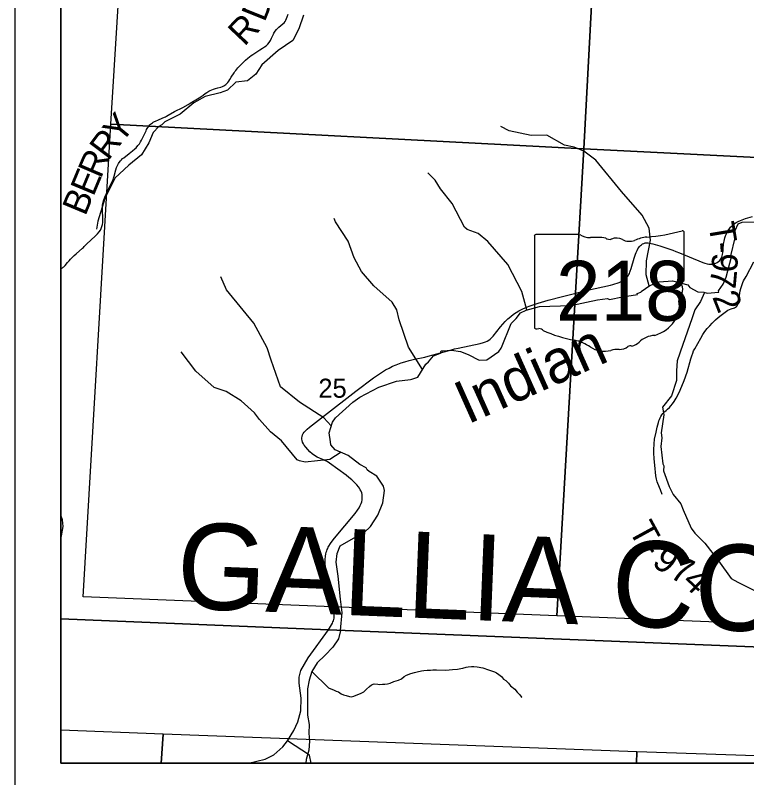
# Model space of a CAD drawing. Extents: x 0 to 34, y 0 to 22.
# Drawn here: x 23.737 to 25.347, y 14.068 to 15.745 of the extents above; entities that cross this region are included whole.
import ezdxf

# ---------------------------------------------------------------- set-up
doc = ezdxf.new("R2010")
doc.units = 0
for name, color, linetype in [('GM_X_County_Road', 7, 'Continuous'), ('GM_X_County_Text', 7, 'Continuous'), ('GM_X_Minor_River', 7, 'Continuous'), ('GM_X_Minor_River_Text', 7, 'Continuous'), ('GM_X_Section', 7, 'Continuous'), ('GM_X_Section_Text', 7, 'Continuous'), ('GM_X_State_Location', 7, 'Continuous'), ('GM_X_State_Route', 7, 'Continuous'), ('GM_X_State_Shield', 7, 'Continuous'), ('GM_X_Township_Road', 7, 'Continuous'), ('GM_X_Township_Road_Text', 7, 'Continuous'), ('SH_Cut_Line', 7, 'Continuous'), ('SH_Data', 7, 'Continuous')]:
    doc.layers.add(name, color=color, linetype=linetype)

msp = doc.modelspace()

# ---------------------------------------------------------------- linework, layer by layer
at = {"layer": 'GM_X_County_Road'}
msp.add_lwpolyline([(24.3882, 14.1), (24.3845, 14.1179), (24.3363, 14.1492)], dxfattribs=at)
at = {"layer": 'GM_X_County_Text'}
msp.add_lwpolyline([(23.8372, 20.6485), (23.8372, 14.4177), (24.4263, 14.3937), (25.7269, 14.3414), (26.0929, 14.3266), (26.1939, 14.3226), (26.568, 14.3076), (26.7502, 14.2997), (27.0716, 14.2873), (27.1862, 14.3829)], dxfattribs=at)
msp.add_lwpolyline([(23.8372, 14.4177), (23.8372, 14.1), (26.9036, 14.1), (26.9358, 14.1416), (26.9861, 14.1972), (27.0318, 14.2519), (27.0716, 14.2873), (26.7502, 14.2997), (26.568, 14.3076), (26.1939, 14.3226), (26.0929, 14.3266), (25.7269, 14.3414), (24.4263, 14.3937)], close=True, dxfattribs=at)
at = {"layer": 'GM_X_Minor_River'}
for points in [[(24.3712, 15.7451), (24.3612, 15.7147), (24.348, 15.6893), (24.3159, 15.6676), (24.2802, 15.636), (24.2667, 15.6156), (24.2481, 15.6006), (24.2227, 15.5976), (24.2041, 15.5804), (24.188, 15.5744), (24.1549, 15.566), (24.1299, 15.5524), (24.1004, 15.5271), (24.0662, 15.5104), (24.0596, 15.5041), (24.0535, 15.5002), (24.0406, 15.4869), (24.0312, 15.4644), (24.0153, 15.4376), (23.987, 15.415), (23.9563, 15.3863), (23.9345, 15.3422), (23.919, 15.2922), (23.9162, 15.2745)], [(25.1325, 15.1497), (25.1253, 15.1742), (25.1262, 15.2049), (25.1355, 15.2506), (25.1322, 15.2769), (25.1168, 15.3055), (25.0711, 15.3574), (25.0146, 15.426), (24.9888, 15.4458), (24.9675, 15.4545), (24.9457, 15.459), (24.9067, 15.4811), (24.8726, 15.4807), (24.8242, 15.491), (24.8059, 15.4999)], [(24.8634, 15.097), (24.8523, 15.1376), (24.8209, 15.1967), (24.777, 15.247), (24.7556, 15.2648), (24.7321, 15.2739), (24.7262, 15.2787), (24.6987, 15.3308), (24.6732, 15.3631), (24.6613, 15.3821), (24.6452, 15.3982)], [(24.6338, 14.966), (24.6023, 15.0152), (24.5822, 15.0754), (24.5768, 15.0969), (24.5667, 15.1143), (24.5262, 15.1501), (24.4992, 15.1814), (24.4827, 15.2115), (24.4699, 15.2484), (24.4417, 15.2903), (24.4388, 15.2978)], [(24.4528, 14.3922), (24.4563, 14.4315), (24.4529, 14.4611), (24.448, 14.5117), (24.4434, 14.5421), (24.4453, 14.5615), (24.4524, 14.5778), (24.4868, 14.5977), (24.5046, 14.6068), (24.5189, 14.6206), (24.5348, 14.6457), (24.5465, 14.6727), (24.5495, 14.6997), (24.5476, 14.7092), (24.5332, 14.7316), (24.5158, 14.7418), (24.5116, 14.7452), (24.5097, 14.7494), (24.4954, 14.7566), (24.47, 14.777), (24.4416, 14.7895), (24.4318, 14.8001), (24.4307, 14.8066), (24.4284, 14.8267), (24.4352, 14.8503), (24.442, 14.8594), (24.4801, 14.8941), (24.4952, 14.9052), (24.5375, 14.9269), (24.5761, 14.9399), (24.6067, 14.9442), (24.6101, 14.9446), (24.6233, 14.9488), (24.6407, 14.9777), (24.6464, 14.9827), (24.6577, 14.9956), (24.6728, 15.0021), (24.6743, 15.0071), (24.6785, 15.0067), (24.6974, 15.0086), (24.7174, 15.0056), (24.734, 14.9985), (24.7582, 14.9867), (24.7753, 14.9871), (24.8013, 15.0058), (24.8066, 15.0127), (24.8074, 15.0146), (24.8289, 15.0667), (24.8394, 15.0781), (24.8493, 15.0903), (24.8613, 15.0964), (24.8912, 15.1045), (24.9596, 15.1065), (25.0182, 15.1188), (25.0409, 15.1223), (25.0447, 15.12), (25.0738, 15.1258), (25.1063, 15.1305), (25.1059, 15.1327), (25.1138, 15.1358), (25.1146, 15.1377), (25.1338, 15.1503), (25.1543, 15.1587), (25.1837, 15.161), (25.2034, 15.1558), (25.217, 15.1524), (25.2215, 15.1463), (25.2397, 15.1365), (25.2529, 15.1358), (25.2601, 15.1335), (25.2854, 15.1362), (25.2847, 15.1389), (25.2949, 15.1533), (25.3017, 15.1686), (25.3137, 15.2138), (25.313, 15.2184), (25.3209, 15.2526), (25.3216, 15.2712), (25.328, 15.2861), (25.3371, 15.2895), (25.3783, 15.2908)], [(24.4327, 14.8417), (24.4162, 14.8594), (24.3624, 14.8942), (24.3211, 14.9281), (24.3006, 14.9865), (24.2919, 15.0137), (24.2622, 15.0678), (24.2389, 15.0963), (24.2024, 15.1411), (24.1893, 15.1697)], [(25.2543, 15.1353), (25.2454, 15.1156), (25.2326, 15.0973), (25.2258, 15.0775), (25.2062, 15.0209), (25.1941, 14.9851), (25.1926, 14.9627), (25.1923, 14.9414), (25.1817, 14.9079), (25.1617, 14.8832), (25.1647, 14.8665), (25.1583, 14.8269), (25.1599, 14.8155), (25.158, 14.7969), (25.1626, 14.7585), (25.1645, 14.754), (25.1637, 14.7429), (25.1766, 14.7084), (25.1853, 14.6913), (25.2016, 14.6708), (25.2073, 14.6575), (25.2247, 14.6173), (25.233, 14.6063), (25.255, 14.5843), (25.2845, 14.5448), (25.3129, 14.5065), (25.3273, 14.4985), (25.3643, 14.48)], [(24.4545, 14.7839), (24.4296, 14.7679), (24.375, 14.762), (24.363, 14.7651), (24.3578, 14.7675), (24.3228, 14.8092), (24.2988, 14.8286), (24.2751, 14.8556), (24.2634, 14.8704), (24.2347, 14.8971), (24.2017, 14.9172), (24.1751, 14.9264), (24.1347, 14.9622), (24.1027, 15.0046)], [(23.8372, 14.5924), (23.8426, 14.6209), (23.8411, 14.635), (23.8372, 14.6458)], [(24.4528, 14.3922), (24.4485, 14.3734), (24.4363, 14.3552), (24.4195, 14.3378), (24.4013, 14.3211), (24.3898, 14.3014), (24.3837, 14.2824), (24.3806, 14.2635), (24.3804, 14.2057), (24.3842, 14.1852), (24.3834, 14.1662), (24.3849, 14.1487), (24.3833, 14.129), (24.3772, 14.1085), (24.3769, 14.1)], [(24.3898, 14.3014), (24.4268, 14.2656), (24.4317, 14.2636), (24.4374, 14.2613), (24.4434, 14.2585), (24.4487, 14.2569), (24.4548, 14.253), (24.4597, 14.2503), (24.4653, 14.2487), (24.4725, 14.2466), (24.4774, 14.2462), (24.482, 14.2473), (24.4912, 14.2509), (24.4973, 14.2531), (24.5042, 14.2572), (24.5104, 14.2632), (24.5169, 14.2688), (24.5215, 14.2725), (24.5269, 14.2743), (24.5349, 14.2738), (24.5394, 14.2734), (24.5455, 14.2737), (24.5504, 14.274), (24.5565, 14.2747), (24.5623, 14.2761), (24.5707, 14.2798), (24.5806, 14.2827), (24.5871, 14.2856), (24.5933, 14.2905), (24.5986, 14.2934), (24.6078, 14.2975), (24.6162, 14.2996), (24.6219, 14.3007), (24.6314, 14.3032), (24.6364, 14.3042), (24.644, 14.3049), (24.6512, 14.3048), (24.6562, 14.3051), (24.6645, 14.3053), (24.6843, 14.305), (24.6923, 14.3057), (24.6991, 14.306), (24.7101, 14.3069), (24.7178, 14.3083), (24.7223, 14.3094), (24.7296, 14.3112), (24.7342, 14.3123), (24.741, 14.3125), (24.7463, 14.3125), (24.7539, 14.312), (24.766, 14.3095), (24.7785, 14.3051), (24.7872, 14.3023), (24.7921, 14.3007), (24.7966, 14.2991), (24.8011, 14.2949), (24.8071, 14.2906), (24.812, 14.2848), (24.8165, 14.2817), (24.8225, 14.2763), (24.8273, 14.2705), (24.8367, 14.2628), (24.8416, 14.2566), (24.8479, 14.2504), (24.8516, 14.245), (24.8521, 14.2443)]]:
    msp.add_lwpolyline(points, dxfattribs=at)
at = {"layer": 'GM_X_Section'}
for points in [[(24.5596, 16.5135), (25.0459, 16.4982), (25.0486, 16.498), (25.0369, 16.3074), (25.0112, 15.8778), (24.9883, 15.4512), (23.9474, 15.5054), (24.0115, 16.5331)], [(26.0395, 15.8225), (26.0137, 15.3999), (24.9883, 15.4512), (25.0112, 15.8778)], [(23.9474, 15.5054), (24.9883, 15.4512), (24.9287, 14.4241), (23.8867, 14.4663)], [(24.9883, 15.4512), (26.0137, 15.3999), (25.9993, 15.1693), (25.9925, 15.0615), (25.9851, 14.9419), (25.9779, 14.8211), (25.9703, 14.6911), (25.9621, 14.5516), (25.9518, 14.384), (24.9287, 14.4241)]]:
    msp.add_lwpolyline(points, close=True, dxfattribs=at)
at = {"layer": 'GM_X_State_Route'}
for points in [[(24.4265, 14.3932), (24.4351, 14.4082), (24.4364, 14.4109), (24.4375, 14.4134), (24.4382, 14.4158), (24.4389, 14.4187), (24.4392, 14.421), (24.4393, 14.4231), (24.4394, 14.4255), (24.4393, 14.4285), (24.439, 14.4314), (24.4385, 14.4344), (24.4354, 14.4511), (24.424, 14.5064), (24.4226, 14.514), (24.4213, 14.5214), (24.4206, 14.5266), (24.4199, 14.5326), (24.4195, 14.5375), (24.4193, 14.541), (24.4192, 14.5446), (24.4193, 14.5479), (24.4194, 14.5506), (24.4197, 14.5533), (24.4201, 14.5563), (24.4208, 14.56), (24.4218, 14.5639), (24.4227, 14.5668), (24.4237, 14.5697), (24.4249, 14.5724), (24.4262, 14.575), (24.4275, 14.5776), (24.4308, 14.5829), (24.4346, 14.5884), (24.4399, 14.595), (24.4852, 14.6495), (24.4905, 14.6565), (24.494, 14.6619), (24.4966, 14.667), (24.4984, 14.6713), (24.4996, 14.6752), (24.5006, 14.6793), (24.5009, 14.6831), (24.5009, 14.6869), (24.5006, 14.6908), (24.4996, 14.6947), (24.4982, 14.6983), (24.4965, 14.7016), (24.4946, 14.7046), (24.4924, 14.7076), (24.4887, 14.7121), (24.4835, 14.7176), (24.4776, 14.7233), (24.4716, 14.7286), (24.4653, 14.7337), (24.4291, 14.7599), (24.4238, 14.7632), (24.4188, 14.7659), (24.4144, 14.7678), (24.4068, 14.7708), (24.4015, 14.7733), (24.396, 14.7764), (24.3906, 14.7804), (24.3856, 14.785), (24.3808, 14.7898), (24.3764, 14.795), (24.3731, 14.7994), (24.3713, 14.8025), (24.3697, 14.8059), (24.3687, 14.8094), (24.3682, 14.8124), (24.3681, 14.8156), (24.3685, 14.8189), (24.3694, 14.8219), (24.3711, 14.8252), (24.3733, 14.8283), (24.3764, 14.8318), (24.3798, 14.8349), (24.385, 14.8391), (24.418, 14.8649), (24.4865, 14.9184), (24.5254, 14.9472), (24.5345, 14.9536), (24.5453, 14.9609), (24.5522, 14.965), (24.5598, 14.9691), (24.5676, 14.9729), (24.5756, 14.9761), (24.5866, 14.9802), (24.5943, 14.9827), (24.6038, 14.9855), (24.6158, 14.9885), (24.6389, 14.9932), (24.6462, 14.9949), (24.657, 14.9979), (24.697, 15.0092), (24.7041, 15.011), (24.7121, 15.0129), (24.7601, 15.0231), (24.7675, 15.025), (24.7721, 15.0266), (24.7756, 15.0282), (24.7794, 15.0306), (24.7824, 15.0328), (24.7853, 15.0352), (24.7892, 15.0393), (24.8054, 15.0598), (24.8101, 15.0655), (24.8156, 15.0714), (24.8214, 15.077), (24.8279, 15.0826), (24.8338, 15.0872), (24.8393, 15.091), (24.8457, 15.0949), (24.8528, 15.0986), (24.8612, 15.1025), (24.8681, 15.1052), (24.8792, 15.1091), (24.888, 15.112), (24.8952, 15.1141), (24.9024, 15.1162), (24.9101, 15.1183), (24.9412, 15.1263), (24.9968, 15.14), (25.047, 15.1516), (25.052, 15.1528), (25.0568, 15.1541), (25.0619, 15.1556), (25.0665, 15.1572), (25.0706, 15.1591), (25.0746, 15.1613), (25.0782, 15.1638), (25.081, 15.1661), (25.0834, 15.1688), (25.0858, 15.1718), (25.0875, 15.1746), (25.0889, 15.1772), (25.09, 15.1796), (25.0908, 15.1819), (25.0928, 15.1877), (25.0995, 15.2109), (25.1008, 15.215), (25.1022, 15.2192), (25.1039, 15.2234), (25.1056, 15.2272), (25.1075, 15.2309), (25.1094, 15.2339), (25.1109, 15.2361), (25.1129, 15.2382), (25.1151, 15.2402), (25.1177, 15.242), (25.1205, 15.2433), (25.1236, 15.2441), (25.1269, 15.2444), (25.1302, 15.2442), (25.1332, 15.2439), (25.1364, 15.2432), (25.1405, 15.2422), (25.1554, 15.2377), (25.1841, 15.2281), (25.1912, 15.2255), (25.199, 15.2225), (25.2506, 15.2009), (25.2551, 15.1994), (25.2596, 15.1983), (25.2633, 15.1977), (25.2668, 15.1975), (25.2698, 15.1977), (25.2732, 15.1981), (25.2763, 15.1989), (25.2789, 15.1999), (25.2818, 15.2013), (25.2848, 15.2034), (25.2878, 15.2059), (25.2895, 15.2079), (25.291, 15.2101), (25.2922, 15.2125), (25.2931, 15.2155), (25.2937, 15.2188), (25.2943, 15.2234), (25.2959, 15.2411), (25.2964, 15.2448), (25.297, 15.2483), (25.2978, 15.2518), (25.2989, 15.2556), (25.3001, 15.2595), (25.3015, 15.2631), (25.3034, 15.2669), (25.3054, 15.2705), (25.3082, 15.2746), (25.3116, 15.2788), (25.3154, 15.2826), (25.3195, 15.2859), (25.3238, 15.2889), (25.3281, 15.2914), (25.3331, 15.2938), (25.3368, 15.2953), (25.3403, 15.2967), (25.3443, 15.298), (25.3593, 15.3021)], [(24.2505, 14.1), (24.2872, 14.1091), (24.3065, 14.1185), (24.326, 14.1363), (24.3363, 14.1492), (24.35, 14.1719), (24.3588, 14.1909), (24.3654, 14.2155), (24.3663, 14.2433), (24.3622, 14.2759), (24.3623, 14.2892), (24.3658, 14.304), (24.3822, 14.3321), (24.4265, 14.3932)]]:
    msp.add_lwpolyline(points, dxfattribs=at)
at = {"layer": 'GM_X_State_Shield'}
for p, q in [((24.8796, 15.259), (24.8796, 15.0589)), ((24.9793, 15.2625), (24.8828, 15.2625)), ((25.2091, 15.1627), (25.2091, 15.2674)), ((25.2091, 15.1628), (25.2091, 15.1627))]:
    msp.add_line(p, q, dxfattribs=at)
for points in [[(23.8372, 14.1725), (23.8372, 14.1), (24.0585, 14.1), (24.0625, 14.1636)], [(24.0585, 14.1), (25.1041, 14.1), (25.1054, 14.1249), (24.0625, 14.1636)], [(25.1041, 14.1), (25.845, 14.1), (25.1054, 14.1249)]]:
    msp.add_lwpolyline(points, close=True, dxfattribs=at)
for centre, major_axis, start_param, end_param in [((24.8833, 15.2594), (0.00382, 0), 1.712693, 3.28349), ((25.0023, 15.2857), (0.037, 0), 4.042523, 4.731795), ((25.0917, 15.5353), (0.3495, 0), 4.814394, 5.042369), ((25.2055, 15.2678), (0.00367, 0), 6.141152, 7.989035), ((25.0146, 15.1501), (0.133, 0), 1.404758, 1.657858), ((25.0448, 15.2605), (0.0107, 0), 3.836095, 5.185415), ((25.0605, 15.2373), (0.0222, 0), 0.950623, 2.079405), ((25.0891, 15.2691), (0.0267, 0), 4.081561, 5.145723), ((25.1363, 15.2013), (0.0703, 0), 1.699011, 2.107814), ((25.2083, 15.155), (0.00568, 0), 1.883978, 3.671073), ((25.2052, 15.1623), (0.00393, 0), 5.05454, 6.418171), ((25.1722, 15.1418), (0.0341, 0), 5.934695, 6.695948), ((25.2223, 15.1189), (0.0248, 0), 2.387724, 3.262537), ((25.1113, 15.1056), (0.0874, 0), 5.101752, 6.440018), ((24.8834, 15.0585), (0.00385, 0), 3.00124, 4.508301), ((24.884, 15.0789), (0.0294, 0), 4.665946, 4.897461), ((24.89, 15.0473), (0.0106, 0), 0.519207, 1.627899), ((25.0238, 15.2271), (0.2524, 0), 4.195997, 4.488961), ((25.1482, 15.0027), (0.0479, 0), 1.647645, 2.488434), ((24.9485, 14.969), (0.079, 0), 0.823519, 1.323587), ((25.0875, 15.0395), (0.0282, 0), 4.937069, 5.64225), ((25.034, 15.0464), (0.0501, 0), 4.026481, 4.996735), ((25.0629, 14.9772), (0.0412, 0), 1.495662, 1.94098), ((25.0666, 15.0314), (0.0267, 0), 4.691044, 5.507374), ((25.0907, 15.012), (0.00752, 0), 1.147584, 2.315152)]:
    msp.add_ellipse(centre, major_axis=major_axis, ratio=0.8, start_param=start_param, end_param=end_param, dxfattribs=at)
at = {"layer": 'GM_X_Township_Road'}
for points in [[(23.8372, 15.1877), (23.8372, 15.1877), (23.8386, 15.1882), (23.84, 15.1888), (23.8414, 15.1896), (23.8428, 15.1907), (23.8443, 15.1919), (23.8458, 15.1932), (23.8472, 15.1947), (23.8525, 15.2013), (23.8557, 15.2051), (23.8588, 15.2084), (23.8625, 15.2123), (23.8672, 15.2166), (23.871, 15.2199), (23.8849, 15.2324), (23.8872, 15.2345), (23.8889, 15.2363), (23.8947, 15.2419), (23.9133, 15.2592), (23.9185, 15.2645), (23.9217, 15.2684), (23.9245, 15.2725), (23.9265, 15.2763), (23.9281, 15.2804), (23.9291, 15.2846), (23.9297, 15.2889), (23.93, 15.2945), (23.9295, 15.3199), (23.9295, 15.3237), (23.9296, 15.3271), (23.9299, 15.3306), (23.9304, 15.3336), (23.9313, 15.3365), (23.9324, 15.34), (23.9334, 15.3427), (23.9345, 15.3453), (23.9362, 15.3488), (23.9379, 15.3526), (23.9485, 15.3747), (23.9512, 15.3807), (23.9526, 15.384), (23.9536, 15.3868), (23.955, 15.3908), (23.9589, 15.4051), (23.9603, 15.4099), (23.9614, 15.4132), (23.9627, 15.4159), (23.9643, 15.4187), (23.9661, 15.4213), (23.9689, 15.4247), (23.9711, 15.4272), (23.9736, 15.4296), (23.9761, 15.4316), (23.9879, 15.4405), (23.9954, 15.4465), (24.0006, 15.4511), (24.0031, 15.4536), (24.0046, 15.4552), (24.0056, 15.4563), (24.0071, 15.4582), (24.0103, 15.4622), (24.013, 15.4663), (24.0149, 15.4701), (24.025, 15.4909), (24.0263, 15.4936), (24.0276, 15.4958), (24.029, 15.498), (24.0304, 15.4998), (24.0318, 15.5016), (24.0335, 15.5036), (24.0352, 15.5053), (24.0373, 15.5071), (24.0392, 15.5086), (24.0411, 15.51), (24.0434, 15.5112), (24.0458, 15.5122), (24.0526, 15.5151), (24.0603, 15.5185), (24.0658, 15.5209), (24.068, 15.5218), (24.0699, 15.5228), (24.0737, 15.5248), (24.088, 15.5329), (24.1058, 15.5421), (24.1181, 15.5489), (24.1221, 15.5514), (24.1416, 15.5635), (24.1462, 15.5665), (24.1507, 15.5695), (24.1553, 15.5727), (24.1592, 15.5752), (24.1632, 15.5776), (24.1663, 15.5792), (24.1697, 15.5808), (24.1735, 15.5823), (24.1781, 15.5837), (24.1833, 15.585), (24.1895, 15.5868), (24.1932, 15.5881), (24.1961, 15.5895), (24.1985, 15.5911), (24.2003, 15.5925), (24.2023, 15.5944), (24.2048, 15.5971), (24.2071, 15.6001), (24.2097, 15.6038), (24.2127, 15.6088), (24.2187, 15.6181), (24.2208, 15.6212), (24.2226, 15.6237), (24.2246, 15.6263), (24.2273, 15.6293), (24.237, 15.6394), (24.2408, 15.6431), (24.2442, 15.6461), (24.2494, 15.6505), (24.2529, 15.6533), (24.2564, 15.656), (24.2599, 15.6585), (24.2758, 15.669), (24.2816, 15.6725), (24.2858, 15.6752), (24.2894, 15.6779), (24.2931, 15.6814), (24.2961, 15.6853), (24.2989, 15.6897), (24.3014, 15.6944), (24.3041, 15.7007), (24.3052, 15.7033), (24.3065, 15.7057), (24.3077, 15.7078), (24.3091, 15.7098), (24.3118, 15.7132), (24.3143, 15.7159), (24.317, 15.7184), (24.3263, 15.7257), (24.3288, 15.7283), (24.3309, 15.731), (24.3328, 15.7342), (24.3344, 15.7378), (24.3358, 15.7416), (24.3376, 15.7475)], [(25.1612, 14.691), (25.157, 14.7014), (25.1513, 14.7153), (25.1502, 14.7186), (25.1492, 14.7216), (25.1483, 14.7247), (25.1475, 14.7286), (25.147, 14.7324), (25.1447, 14.7553), (25.143, 14.7691), (25.1424, 14.7827), (25.1422, 14.7863), (25.1424, 14.7894), (25.1432, 14.8025), (25.1434, 14.8055), (25.1439, 14.8095), (25.1443, 14.813), (25.1477, 14.8281), (25.15, 14.8391), (25.1512, 14.8442), (25.1525, 14.8491), (25.1536, 14.8528), (25.1548, 14.8562), (25.1563, 14.8595), (25.158, 14.8628), (25.16, 14.8662), (25.162, 14.8689), (25.1642, 14.8711), (25.1668, 14.8732), (25.1696, 14.8756), (25.1728, 14.8784), (25.1768, 14.8823), (25.18, 14.886), (25.1835, 14.8903), (25.1873, 14.8957), (25.1917, 14.9029), (25.1956, 14.9096), (25.2006, 14.9204), (25.2093, 14.9417), (25.216, 14.9597), (25.224, 14.989), (25.2261, 14.9962), (25.228, 15.0015), (25.2301, 15.0066), (25.2326, 15.0116), (25.246, 15.0348), (25.2504, 15.0425), (25.2548, 15.0493), (25.2602, 15.0559), (25.2654, 15.0621), (25.2708, 15.0678), (25.2784, 15.0752), (25.2842, 15.08), (25.2909, 15.0856), (25.2963, 15.0899), (25.3023, 15.0942), (25.3054, 15.0961), (25.309, 15.0979), (25.3127, 15.0994), (25.3197, 15.1018), (25.3222, 15.1029), (25.3244, 15.1043), (25.326, 15.1062), (25.3273, 15.1085), (25.3283, 15.1114), (25.329, 15.1146), (25.3297, 15.1186), (25.3319, 15.1334), (25.3328, 15.1386), (25.334, 15.1437), (25.3353, 15.1484), (25.3369, 15.1528), (25.3385, 15.1569), (25.3402, 15.1605), (25.3455, 15.1707), (25.3625, 15.2029)]]:
    msp.add_lwpolyline(points, dxfattribs=at)
at = {"layer": 'SH_Cut_Line'}
msp.add_lwpolyline([(23.8372, 20.9), (23.8372, 14.4177), (24.4263, 14.3937), (25.7269, 14.3414), (26.0929, 14.3266), (26.1939, 14.3226), (26.568, 14.3076), (26.7502, 14.2997), (27.0716, 14.2873), (27.1862, 14.3829)], dxfattribs=at)
msp.add_lwpolyline([(23.8372, 14.4177), (23.8372, 14.1), (26.9036, 14.1), (26.9358, 14.1416), (26.9861, 14.1972), (27.0318, 14.2519), (27.0716, 14.2873), (26.7502, 14.2997), (26.568, 14.3076), (26.1939, 14.3226), (26.0929, 14.3266), (25.7269, 14.3414), (24.4263, 14.3937)], close=True, dxfattribs=at)
at = {"layer": 'SH_Data'}
for points in [[(23.7372, 21), (30.7372, 21), (30.7372, 14), (23.7372, 14)], [(23.8372, 20.9), (30.6372, 20.9), (30.6372, 14.1), (23.8372, 14.1)]]:
    msp.add_lwpolyline(points, close=True, dxfattribs=at)

# ---------------------------------------------------------------- texts
at = {"layer": 'GM_X_County_Text'}
msp.add_text('GALLIA COUNTY', height=0.189394, rotation=357.6921, dxfattribs=at).set_placement((24.0901, 14.4413))
at = {"layer": 'GM_X_Minor_River_Text'}
msp.add_text('Indian', height=0.09469, rotation=24.1322, dxfattribs=at).set_placement((24.7325, 14.8444))
at = {"layer": 'GM_X_Section_Text'}
msp.add_text('25', height=0.04186, rotation=0, dxfattribs=at).set_placement((24.4043, 14.9038))
at = {"layer": 'GM_X_State_Location'}
for s in ['s', 'r']:
    msp.add_text(s, height=0.000189, dxfattribs=at).set_placement((25.0406, 15.1456))
msp.add_text('218', height=0.000189, rotation=0, dxfattribs=at).set_placement((24.9738, 15.1319))
at = {"layer": 'GM_X_State_Shield'}
msp.add_text('218', height=0.13184, dxfattribs=at).set_placement((24.9272, 15.073))
at = {"layer": 'GM_X_Township_Road_Text'}
for s, rotation, p in [('D', 68.2671, (24.286, 15.7281)), ('R', 46.5194, (24.2415, 15.6749)), ('Y', 50.5662, (23.9695, 15.4604)), ('R', 53.1762, (23.942, 15.4236)), ('R', 66.8703, (23.9255, 15.3838)), ('E', 67.4314, (23.9092, 15.3446)), ('B', 67.4379, (23.8913, 15.3016)), ('T', 279.4324, (25.2625, 15.2853)), ('-', 274.7672, (25.2693, 15.2446)), ('9', 267.0533, (25.2712, 15.2234)), ('7', 264.7365, (25.2695, 15.189)), ('2', 291.7052, (25.2704, 15.1256)), ('T', 298.645, (25.0863, 14.6131)), ('-', 305.2595, (25.1104, 14.5698)), ('9', 321.4887, (25.1359, 14.538)), ('7', 333.6828, (25.1744, 14.5092)), ('4', 316.5071, (25.2021, 14.4962))]:
    msp.add_text(s, height=0.0568, rotation=rotation, dxfattribs=at).set_placement(p)

doc.saveas('drawing.dxf')
